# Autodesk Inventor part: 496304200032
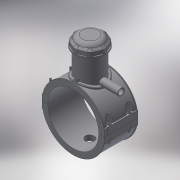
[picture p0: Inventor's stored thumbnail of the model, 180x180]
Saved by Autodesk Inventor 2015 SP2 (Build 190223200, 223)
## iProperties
Created: 2017-07
Part Number: 496304200032
Material: Generic
Description: PLASSON TAPPING SADDLE 200x32
Document SubType Name: Modeling
Designer: KIM
Mass: 1279.96 g
Surface Area: 3064.51 cm^2
Volume: 1279.96 cm^3
Density: 1 g/cm^3
Appearance: Default
Author: KIM
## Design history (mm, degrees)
derived "496304.ipt"
feature "Solid1::496304.ipt"
feature "Solid2::496304.ipt"
feature "Solid4::496304.ipt"
feature "Solid5::496304.ipt"
tag "TaggingFeature1" dims "B_" = 202
body "Solid1"
body "Solid2"
other parameters: "L_" = 176, "d_t" = 6, "H_2" = 177, "H_1" = 56, "d_1" = 32, "H_" = 132, "d1" = 228, "d148" = 3, "d160" = 3, "d169" = 3, "d192" = 5.6, "d2" = 262.6, "d4" = 176, "d5" = 0, "d6" = 0.1, "d8" = 0, "d19" = 6, "d20" = 6, "d21" = 105.6, "d23" = 0, "d24" = 52.8, "d26" = 0, "d29" = 3, "d30" = 66.66667, "d31" = 6, "d32" = 0, "d33" = 0, "d34" = 0.6, "d40" = 118.56, "d43" = 0, "d45" = 0, "d47" = 219.6, "d70" = 15, "d72" = 0, "d73" = 6, "d75" = 5, "d76" = 0, "d79" = 15, "d80" = 70.4, "d82" = 5 deg, "d84" = 4, "d85" = 14, "d86" = 0, "d87" = 3, "d88" = 0, "d89" = 1, "d90" = 1, "d91" = 140.8, "d92" = 0, "d93" = 0.5, "d94" = 105.26316, "d96" = 232.56, "d97" = 3.52, "d98" = 0, "d102" = 2, "d120" = 140 deg, "d121" = 24.228, "d122" = 20 deg, "d123" = 456, "d124" = 136.8, "d126" = 0, "d143" = 206, "d145" = 21.53846, "d149" = 3, "d150" = 23.69231, "d153" = 176, "d154" = 0, "d156" = 114, "d157" = 160 deg, "d159" = 5.6, "d161" = 3, "d162" = 105.6, "d163" = 0, "d168" = 111.21951, "d170" = 3, "d172" = 0, "d173" = 1, "d176" = 20 deg, "d177" = 14, "d178" = 28, "d180" = 0, "d183" = 11.2, "d184" = 11.2, "d185" = 57.2, "d186" = 57.2, "d187" = 114, "d188" = 8.4, "d189" = 14, "d190" = 0, "d191" = 171, "d193" = 5.6, "d194" = 6.16, "d195" = 90 deg, "d197" = 0, "d199" = 0, "d200" = 14, "d202" = 0, "d203" = 177, "d204" = 76, "d205" = 56, "d206" = 68, "d207" = 132.75, "d208" = 138.06, "d209" = 164.61, "d210" = 68.8, "d212" = 64, "d213" = 36, "d216" = 0, "d219" = 4, "d224" = 0, "d230" = 4, "d233" = 6, "d236" = 101, "d237" = 52.8, "d238" = 6.02433, "d240" = 52.8, "d241" = 52.8, "d242" = 52.8, "d243" = 6, "d244" = 52.8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
